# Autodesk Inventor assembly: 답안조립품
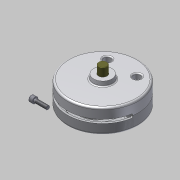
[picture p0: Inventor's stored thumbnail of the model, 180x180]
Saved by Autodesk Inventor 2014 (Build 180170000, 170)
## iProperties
Created: 2015-06
Part Number: 답안조립품
Document SubType Name: Assembly
Designer: MYHOME
Author: MYHOME
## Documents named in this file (7)
- C:\Documents and Settings\MYHOME\바탕 화면\450631V1029\답안조립품.iam
- C:\Documents and Settings\MYHOME\바탕 화면\450631V1029\본체.ipt
- C:\Documents and Settings\MYHOME\바탕 화면\450631V1029\덮개.ipt
- C:\Documents and Settings\MYHOME\바탕 화면\450631V1029\축.ipt
- C:\Documents and Settings\MYHOME\바탕 화면\450631V1029\베어링62_22.ipt
- C:\Documents and Settings\MYHOME\바탕 화면\450631V1029\슬라이더2.ipt
- C:\Documents and Settings\MYHOME\바탕 화면\450631V1029\M10x35.ipt
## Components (3 placed, 2 different names)
1. KS B 2023 62/22 - 22 x 50 x 14:1
2. KS B 2023 62/22 - 22 x 50 x 14:2
3. KS B 1003 - 미터 M 10 x 35:1
